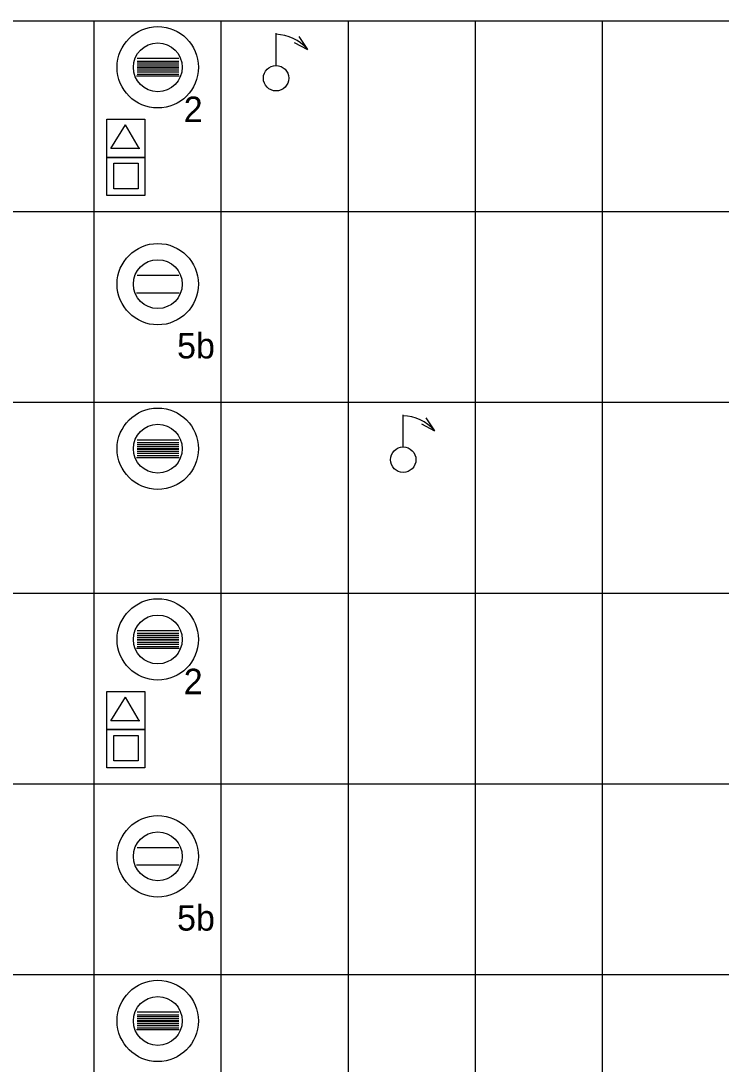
# Model space of a CAD drawing. Extents: x -28 to 822, y 61 to 665.
# Drawn here: x 137.4 to 192.5, y 299.7 to 381.7 of the extents above; entities that cross this region are included whole.
import ezdxf

# ---------------------------------------------------------------- set-up
doc = ezdxf.new("R2010")
doc.units = 0

# ---------------------------------------------------------------- blocks, each defined once
blk = doc.blocks.new('HR3')
for radius in [2.5, 1.5]:
    blk.add_circle((0, 0), radius)

msp = doc.modelspace()

# ---------------------------------------------------------------- linework, layer by layer
for p, q in [((5.068, 381.738), (540.616, 381.738)), ((5.068, 381.738), (293.116, 381.738)), ((5.068, 381.738), (293.116, 381.738)), ((143.116, 381.738), (143.116, 141.738)), ((153.116, 381.738), (153.116, 111.738)), ((163.116, 381.738), (163.116, 111.738)), ((173.116, 381.738), (173.116, 111.738)), ((183.116, 381.738), (183.116, 111.738)), ((157.458, 378.227), (157.458, 380.76)), ((158.886, 380.035), (159.928, 379.485)), ((159.241, 380.51), (159.928, 379.485)), ((146.53, 378.794), (149.801, 378.794)), ((146.53, 378.571), (149.801, 378.571)), ((146.53, 378.433), (149.801, 378.433)), ((146.53, 378.273), (149.801, 378.273)), ((146.53, 378.114), (149.801, 378.114)), ((146.53, 378.05), (149.801, 378.05)), ((146.53, 377.885), (149.801, 377.885)), ((146.53, 377.726), (149.801, 377.726)), ((146.53, 377.543), (149.801, 377.543)), ((146.481, 377.409), (149.85, 377.409)), ((144.461, 371.699), (145.623, 373.552)), ((146.728, 371.672), (145.623, 373.552)), ((146.743, 371.699), (144.461, 371.699)), ((5.068, 366.738), (292.72, 366.738)), ((143.116, 366.738), (143.116, 111.738)), ((146.53, 361.738), (149.801, 361.738)), ((146.481, 360.353), (149.85, 360.353)), ((5.068, 351.738), (540.616, 351.738)), ((167.458, 348.227), (167.458, 350.76)), ((169.241, 350.51), (169.928, 349.485)), ((168.886, 350.035), (169.928, 349.485)), ((146.53, 348.794), (149.801, 348.794)), ((146.53, 348.571), (149.801, 348.571)), ((146.53, 348.433), (149.801, 348.433)), ((146.53, 348.273), (149.801, 348.273)), ((146.53, 348.114), (149.801, 348.114)), ((146.53, 348.05), (149.801, 348.05)), ((146.481, 347.409), (149.85, 347.409)), ((146.53, 347.885), (149.801, 347.885)), ((146.53, 347.726), (149.801, 347.726)), ((146.53, 347.543), (149.801, 347.543)), ((5.068, 336.738), (540.616, 336.738)), ((5.068, 336.738), (293.116, 336.738)), ((5.068, 336.738), (293.116, 336.738)), ((146.53, 333.794), (149.801, 333.794)), ((146.53, 333.571), (149.801, 333.571)), ((146.53, 333.433), (149.801, 333.433)), ((146.53, 333.273), (149.801, 333.273)), ((146.481, 332.409), (149.85, 332.409)), ((146.53, 333.114), (149.801, 333.114)), ((146.53, 333.05), (149.801, 333.05)), ((146.53, 332.885), (149.801, 332.885)), ((146.53, 332.726), (149.801, 332.726)), ((146.53, 332.543), (149.801, 332.543)), ((144.461, 326.699), (145.623, 328.552)), ((146.728, 326.672), (145.623, 328.552)), ((146.743, 326.699), (144.461, 326.699)), ((5.068, 321.738), (292.72, 321.738)), ((146.53, 316.738), (149.801, 316.738)), ((146.481, 315.353), (149.85, 315.353)), ((5.068, 306.738), (540.616, 306.738)), ((146.53, 303.794), (149.801, 303.794)), ((146.53, 303.571), (149.801, 303.571)), ((146.53, 303.433), (149.801, 303.433)), ((146.53, 303.273), (149.801, 303.273)), ((146.53, 303.114), (149.801, 303.114)), ((146.53, 303.05), (149.801, 303.05)), ((146.53, 302.885), (149.801, 302.885)), ((146.481, 302.409), (149.85, 302.409)), ((146.53, 302.726), (149.801, 302.726)), ((146.53, 302.543), (149.801, 302.543))]:
    msp.add_line(p, q)
for points in [[(147.139, 371), (144.139, 371), (144.139, 374), (147.139, 374)], [(147.139, 368), (144.139, 368), (144.139, 371), (147.139, 371)], [(146.618, 368.541), (144.691, 368.541), (144.691, 370.544), (146.618, 370.544)], [(147.139, 326), (144.139, 326), (144.139, 329), (147.139, 329)], [(147.139, 323), (144.139, 323), (144.139, 326), (147.139, 326)], [(146.618, 323.541), (144.691, 323.541), (144.691, 325.544), (146.618, 325.544)]]:
    msp.add_lwpolyline(points, close=True)
for centre in [(157.458, 377.227), (167.458, 347.227)]:
    msp.add_circle(centre, 1)
for centre in [(157.36, 377.32), (167.36, 347.32)]:
    msp.add_arc(centre, 3.362, 40.87786, 88.37535)

# ---------------------------------------------------------------- block references
at = {"xscale": 1.2800000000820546, "yscale": 1.2800000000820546}
for p in [(148.157, 378.087), (148.157, 361.031), (148.157, 348.087), (148.157, 333.087), (148.157, 316.031), (148.157, 303.087)]:
    msp.add_blockref('HR3', p, dxfattribs=at)

# ---------------------------------------------------------------- texts
for s, p in [('2', (150.198, 373.784)), ('5b', (149.672, 355.19)), ('2', (150.198, 328.784)), ('5b', (149.672, 310.19))]:
    msp.add_text(s, height=2).set_placement(p)

doc.saveas('drawing.dxf')
